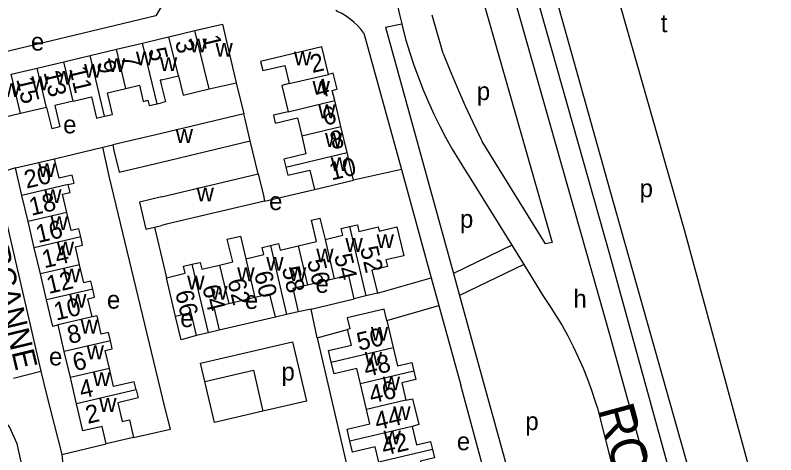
# Model space of a CAD drawing. Extents: x 157646 to 159241, y 379213 to 381217.
# Drawn here: x 158967.4 to 159137, y 380874.9 to 380973 of the extents above; entities that cross this region are included whole.
import ezdxf

# ---------------------------------------------------------------- set-up
doc = ezdxf.new("R2010")
doc.units = 0
for name, color, linetype in [('BLT_Basislijn', 7, 'Continuous'), ('BLT_Bebouwing', 7, 'Continuous'), ('BLT_Centroide', 7, 'Continuous'), ('BLT_Huisnummer', 7, 'Continuous'), ('BLT_Huisnummer_ tussenligend', 7, 'Continuous'), ('BLT_Onderverdeling_panden', 7, 'Continuous'), ('BLT_Straatnaam', 7, 'Continuous'), ('BLT_Straatnaam_hoofdweg', 7, 'Continuous')]:
    doc.layers.add(name, color=color, linetype=linetype)

msp = doc.modelspace()

# ---------------------------------------------------------------- linework, layer by layer
at = {"layer": 'BLT_Basislijn'}
for p, q in [((159062.85, 380964.45), (159060.36, 380973)), ((159049.95, 380970.32), (159053.58, 380971.02)), ((159049.95, 380970.32), (159065.11, 380915.31)), ((159045.13, 380968.99), (159053.52, 380938.55)), ((159016.64, 380957.89), (159018.38, 380950.98)), ((159021.58, 380937.58), (159019.82, 380944.91)), ((158976.19, 380940.93), (158986.93, 380943.49)), ((158986.93, 380943.49), (158989.15, 380944.01)), ((158967.46, 380938.89), (158962.92, 380937.51)), ((159053.52, 380938.55), (159042.86, 380936.15)), ((159053.52, 380938.55), (159060.19, 380914.35)), ((158962.92, 380937.51), (158973.14, 380893.55)), ((159068.63, 380937), (159078.15, 380921.62)), ((159023.02, 380931.49), (159034.13, 380934.08)), ((158998.47, 380925.69), (159001.1, 380914.38)), ((159078.15, 380921.62), (159065.11, 380915.31)), ((159078.15, 380921.62), (159080.79, 380917.35)), ((159080.79, 380917.35), (159066.46, 380910.41)), ((159080.79, 380917.35), (159085.09, 380910.41)), ((159048.15, 380910.92), (159060.19, 380914.35)), ((159060.19, 380914.35), (159061.89, 380908.18)), ((159065.11, 380915.31), (159066.46, 380910.41)), ((159033.39, 380907.39), (159042.99, 380909.7)), ((159066.46, 380910.41), (159071.61, 380891.71)), ((159033.39, 380907.39), (159030.52, 380906.8)), ((159034.75, 380900.98), (159033.39, 380907.39)), ((159050.25, 380904.84), (159061.89, 380908.18)), ((159061.89, 380908.18), (159066.79, 380890.38)), ((159025.41, 380905.59), (159012.87, 380902.69)), ((159034.75, 380900.98), (159041.52, 380902.85)), ((159034.75, 380900.98), (159054.42, 380816.35)), ((158967.04, 380891.93), (158973.14, 380893.55)), ((159084.78, 380823.3), (159066.79, 380890.38)), ((159097.22, 380885.26), (159118.39, 380801.95)), ((158977.78, 380874.89), (158987.68, 380877.29))]:
    msp.add_line(p, q, dxfattribs=at)
for points in [[(159061.42, 381122.18), (159087.3, 381027.91), (159116.68, 380924.86), (159137, 380849.84)], [(159051.94, 381105.75), (159100, 380933.91), (159125.11, 380844.8)], [(159009.95, 380977.12), (159000.45, 380975.73), (158998.72, 380972.84), (158953.4, 380962)], [(159126.48, 380806.41), (159129.85, 380807.86), (159130.83, 380808.7), (159130.78, 380809.42), (159115.53, 380863.06), (159100, 380919.55), (159083.47, 380977.99), (159078.6, 380977.14)], [(159078.6, 380977.14), (159100, 380901.47), (159124.92, 380811.25), (159126.48, 380806.41)], [(159052.45, 380976.01), (159053.07, 380973.13), (159053.58, 380971.02)], [(159071.84, 380975.87), (159087.11, 380922.26), (159085.67, 380921.97), (159071.52, 380944.8)], [(159045.13, 380968.99), (159044.45, 380969.86), (159043.72, 380970.67), (159042.92, 380971.42), (159042.08, 380972.12), (159041.18, 380972.75), (159040.24, 380973.32), (159039.27, 380973.82), (159038.87, 380973.99)], [(159053.58, 380971.02), (159053.76, 380970.27), (159054.53, 380967.42), (159055.38, 380964.6), (159056.31, 380961.8), (159057.31, 380959.03), (159058.39, 380956.29), (159059.54, 380953.57), (159060.76, 380950.89), (159062.06, 380948.24), (159063.42, 380945.63), (159064.86, 380943.06), (159066.37, 380940.53), (159067.94, 380938.03), (159068.63, 380937)], [(159062.85, 380964.45), (159064.38, 380960.57), (159065.99, 380956.71), (159067.67, 380952.89), (159069.42, 380949.09), (159071.25, 380945.34), (159071.52, 380944.8)], [(158993.76, 380878.72), (159002, 380880.56), (159000.73, 380885.48), (158988.42, 380936.73), (158986.93, 380943.49)], [(159085.09, 380910.41), (159086.57, 380908.21), (159087.99, 380905.98), (159089.34, 380903.7), (159090.62, 380901.38), (159091.82, 380899.03), (159092.96, 380896.64), (159094.02, 380894.21), (159095.01, 380891.76), (159095.92, 380889.27), (159096.76, 380886.76), (159097.22, 380885.26)], [(159007.82, 380901.49), (159004.38, 380900.49), (159003.14, 380905.73)], [(159008.74, 380895.28), (159029.23, 380900.1), (159032.35, 380886.86), (159022.65, 380884.58)], [(159009.7, 380891.19), (159008.74, 380895.28)], [(159009.7, 380891.19), (159020.5, 380893.73), (159022.65, 380884.58)], [(158973.14, 380893.55), (158974.36, 380888.3), (158977.78, 380874.89)], [(159022.65, 380884.58), (159011.86, 380882.04), (159009.7, 380891.19)], [(159071.61, 380891.71), (159098.09, 380795.96), (159099.25, 380793.36), (159118.39, 380801.95)], [(158969.46, 380869.92), (158967.87, 380877.27), (158966.12, 380881.08), (158963.78, 380883.86), (158961.67, 380885.68), (158958.02, 380887.53)], [(158977.78, 380874.89), (158978.11, 380872.12), (158969.46, 380869.92)]]:
    msp.add_lwpolyline(points, dxfattribs=at)
at = {"layer": 'BLT_Bebouwing'}
for p, q in [((159007.49, 380969.53), (159013.63, 380970.99)), ((159001.68, 380968.14), (159007.49, 380969.53)), ((158989.98, 380965.37), (158995.81, 380966.75)), ((158995.81, 380966.75), (159000.01, 380967.74)), ((159000.01, 380967.74), (159001.68, 380968.14)), ((158984.09, 380963.98), (158989.98, 380965.37)), ((158978.21, 380962.58), (158984.09, 380963.98)), ((158972.32, 380961.18), (158978.21, 380962.58)), ((158966.5, 380959.81), (158972.32, 380961.18)), ((159000, 380958.57), (159003.79, 380959.47)), ((158999.03, 380953.19), (159000, 380953.42)), ((159040.02, 380948.11), (159038.65, 380953.91)), ((158974.41, 380952.38), (158975.54, 380947.59)), ((159018.38, 380950.98), (159000, 380946.58)), ((159041.4, 380942.3), (159040.02, 380948.11)), ((159000, 380946.58), (158989.15, 380944.01)), ((159000, 380940.18), (159019.82, 380944.91)), ((159042.86, 380936.15), (159041.4, 380942.3)), ((158968.9, 380932.75), (158967.46, 380938.89)), ((159000, 380932.44), (159021.58, 380937.58)), ((159034.13, 380934.08), (159042.86, 380936.15)), ((158970.27, 380926.91), (158968.9, 380932.75)), ((158971.64, 380921.04), (158970.27, 380926.91)), ((158998.47, 380925.69), (159000, 380926.06)), ((158973.01, 380915.22), (158971.64, 380921.04)), ((158974.37, 380909.41), (158973.01, 380915.22)), ((159003.14, 380905.73), (159001.1, 380914.38)), ((159038.55, 380914.13), (159032.59, 380912.72)), ((159048.15, 380910.92), (159045.57, 380910.31)), ((159020.86, 380909.96), (159015, 380908.57)), ((159045.57, 380910.31), (159042.99, 380909.7)), ((159027.93, 380906.19), (159025.41, 380905.59)), ((159030.52, 380906.8), (159027.93, 380906.19)), ((158978.34, 380897.91), (158976.95, 380903.84)), ((159012.87, 380902.69), (159010.39, 380902.1)), ((159010.39, 380902.1), (159007.82, 380901.49)), ((158979.71, 380892.08), (158978.34, 380897.91)), ((158981.08, 380886.24), (158979.71, 380892.08)), ((159045.72, 380884.95), (159044.36, 380890.71))]:
    msp.add_line(p, q, dxfattribs=at)
for points in [[(159013.63, 380970.99), (159014.72, 380966.11), (159016.64, 380957.89)], [(159037.26, 380959.77), (159035.81, 380965.89), (159022.12, 380962.65), (159022.6, 380960.6), (159027.5, 380961.76), (159028.47, 380957.69)], [(159038.65, 380953.91), (159038.11, 380956.19), (159039.18, 380956.44), (159038.33, 380960.03), (159037.26, 380959.77)], [(159000, 380958.57), (158999.73, 380958.5), (158999.97, 380957.5)], [(159003.79, 380959.47), (159004.82, 380955.12), (159010.65, 380956.51)], [(158987.31, 380950.41), (158989.1, 380950.83), (158987.97, 380955.64), (158992.05, 380956.61)], [(158992.05, 380956.61), (158995.11, 380957.33), (158995.96, 380953.73), (158996.99, 380953.98), (158997.28, 380952.78), (158999.03, 380953.19)], [(158999.97, 380957.5), (159000.88, 380953.63), (159000, 380953.42)], [(159010.65, 380956.51), (159016.64, 380957.89)], [(159028.47, 380957.69), (159026.84, 380957.3), (159028.23, 380951.44)], [(158980.3, 380953.77), (158976.22, 380952.81), (158977.35, 380948.02), (158975.54, 380947.59)], [(158980.3, 380953.77), (158984.38, 380954.74), (158985.51, 380949.98), (158987.31, 380950.41)], [(158974.41, 380952.38), (158968.59, 380951)], [(159028.23, 380951.44), (159024.98, 380950.67), (159025.4, 380948.88), (159030.34, 380950.05), (159031.29, 380946.04)], [(158968.59, 380951), (158964.59, 380950.05), (158964.96, 380948.48), (158963.19, 380948.06)], [(159019.82, 380944.91), (159018.67, 380949.77), (159018.38, 380950.98)], [(159031.29, 380946.04), (159032.24, 380942.03), (159027.33, 380940.87), (159027.75, 380939.06)], [(158989.15, 380944.01), (158989.42, 380942.81), (158990.57, 380937.95), (159000, 380940.18)], [(158967.46, 380938.89), (158972.33, 380940.03), (158976.19, 380940.93)], [(158979.21, 380935.17), (158980.53, 380935.49), (158980.12, 380937.27), (158978.79, 380936.96), (158977.21, 380936.59), (158976.19, 380940.93)], [(159027.75, 380939.06), (159028.18, 380937.25), (159033.1, 380938.42), (159034.13, 380934.08)], [(159021.58, 380937.58), (159022.73, 380932.71), (159023.02, 380931.49)], [(158978.93, 380928.94), (158977.98, 380933), (158979.63, 380933.39), (158979.21, 380935.17)], [(159000, 380932.44), (158995.12, 380931.27), (158996.55, 380925.24), (158998.47, 380925.69)], [(159023.02, 380931.49), (159001.42, 380926.39), (159000, 380926.06)], [(158982, 380923.47), (158981.57, 380925.29), (158979.88, 380924.89), (158978.93, 380928.94)], [(159030.52, 380921.46), (159034.59, 380922.43), (159033.45, 380927.25), (159035.34, 380927.69), (159036.48, 380922.89)], [(159041.91, 380925.78), (159043.7, 380926.21), (159044.06, 380924.72), (159048.34, 380925.73), (159048.57, 380924.79), (159052.53, 380925.73), (159054.05, 380919.3), (159050.08, 380918.36), (159050.42, 380916.92), (159046.93, 380916.1), (159048.15, 380910.92)], [(159036.48, 380922.89), (159040.48, 380923.84), (159040.12, 380925.36), (159041.91, 380925.78)], [(158981.75, 380917.27), (158980.81, 380921.28), (158982.42, 380921.66), (158982, 380923.47)], [(159012.96, 380917.21), (159015.9, 380917.9), (159014.7, 380922.98), (159017.62, 380923.67), (159018.82, 380918.61)], [(159018.82, 380918.61), (159022.86, 380919.57), (159022.49, 380921.13), (159024.3, 380921.56)], [(159024.3, 380921.56), (159026.11, 380921.99), (159026.46, 380920.5), (159030.52, 380921.46)], [(159006.78, 380917.37), (159008.62, 380917.8), (159008.98, 380916.27), (159012.96, 380917.21)], [(158984.68, 380911.83), (158984.26, 380913.62), (158982.69, 380913.26), (158981.75, 380917.27)], [(159001.1, 380914.38), (159005.32, 380915.37), (159004.95, 380916.93), (159006.78, 380917.37)], [(159042.99, 380909.7), (159041.77, 380914.89), (159038.55, 380914.13)], [(159032.59, 380912.72), (159029.3, 380911.94), (159030.52, 380906.8)], [(158984.54, 380905.62), (158983.59, 380909.68), (158985.1, 380910.04), (158984.68, 380911.83)], [(159025.41, 380905.59), (159024.19, 380910.74), (159020.86, 380909.96)], [(158976.95, 380903.84), (158975.77, 380903.46), (158974.37, 380909.41)], [(159015, 380908.57), (159011.67, 380907.79), (159012.87, 380902.69)], [(159050.25, 380904.84), (159049.65, 380907.36), (159041.4, 380905.41), (159041.98, 380902.96), (159041.52, 380902.85)], [(158988.63, 380900.33), (158988.21, 380902.13), (158986.6, 380901.75), (158985.64, 380905.87), (158984.54, 380905.62)], [(159007.82, 380901.49), (159006.63, 380906.56), (159003.14, 380905.73)], [(159050.25, 380904.84), (159051.67, 380898.79)], [(159037.88, 380895.53), (159037.27, 380898.1), (159042.36, 380899.3), (159041.52, 380902.85)], [(158988.4, 380894.12), (158987.46, 380898.15), (158989.05, 380898.52), (158988.63, 380900.33)], [(159051.67, 380898.79), (159052.65, 380894.68), (159055.87, 380895.44), (159056.32, 380893.54)], [(159044.36, 380890.71), (159043.55, 380894.15), (159038.49, 380892.96), (159037.88, 380895.53)], [(158994.39, 380889.33), (158993.96, 380891.17), (158989.35, 380890.09), (158988.4, 380894.12)], [(159056.32, 380893.54), (159056.77, 380891.64), (159053.61, 380890.89), (159054.52, 380887.03)], [(158994.39, 380889.33), (158994.81, 380887.55), (158990.26, 380886.48), (158991.25, 380882.26), (158992.85, 380882.63), (158993.76, 380878.72)], [(159054.52, 380887.03), (159056, 380887.38), (159057.37, 380881.63), (159055.92, 380881.16)], [(158987.68, 380877.29), (158986.76, 380881.2), (158982.49, 380880.2), (158981.08, 380886.24)], [(159042.04, 380877.88), (159041.4, 380880.56), (159046.48, 380881.77), (159045.72, 380884.95)], [(159055.92, 380881.16), (159056.88, 380877.1), (159060.04, 380877.85), (159060.47, 380876.02)], [(158993.76, 380878.72), (158987.68, 380877.29)], [(159048.48, 380873.18), (159047.67, 380876.61), (159042.62, 380875.41), (159042.04, 380877.88)], [(159060.47, 380876.02), (159060.91, 380874.18), (159057.76, 380873.44), (159058.68, 380869.58)]]:
    msp.add_lwpolyline(points, dxfattribs=at)
at = {"layer": 'BLT_Onderverdeling_panden'}
for p, q in [((159010.65, 380956.51), (159007.49, 380969.53)), ((158999.03, 380953.19), (158995.81, 380966.75)), ((159003.79, 380959.47), (159001.68, 380968.14)), ((158992.05, 380956.61), (158989.98, 380965.37)), ((158987.31, 380950.41), (158984.09, 380963.98)), ((158980.3, 380953.77), (158978.21, 380962.58)), ((158974.41, 380952.38), (158972.32, 380961.18)), ((158968.59, 380951), (158966.5, 380959.81)), ((159028.47, 380957.69), (159037.26, 380959.77)), ((159028.23, 380951.44), (159038.65, 380953.91)), ((159031.29, 380946.04), (159040.02, 380948.11)), ((159027.75, 380939.06), (159041.4, 380942.3)), ((158979.21, 380935.17), (158968.9, 380932.75)), ((158978.93, 380928.94), (158970.27, 380926.91)), ((159041.91, 380925.78), (159045.57, 380910.31)), ((158982, 380923.47), (158971.64, 380921.04)), ((159036.48, 380922.89), (159038.55, 380914.13)), ((159024.3, 380921.56), (159027.93, 380906.19)), ((159030.52, 380921.46), (159032.59, 380912.72)), ((159018.82, 380918.61), (159020.86, 380909.96)), ((158981.75, 380917.27), (158973.01, 380915.22)), ((159006.78, 380917.37), (159010.39, 380902.1)), ((159012.96, 380917.21), (159015, 380908.57)), ((158984.68, 380911.83), (158974.37, 380909.41)), ((158984.54, 380905.62), (158976.95, 380903.84)), ((158988.63, 380900.33), (158978.34, 380897.91)), ((159037.88, 380895.53), (159051.67, 380898.79)), ((158988.4, 380894.12), (158979.71, 380892.08)), ((159056.32, 380893.54), (159044.36, 380890.71)), ((158994.39, 380889.33), (158981.08, 380886.24)), ((159054.52, 380887.03), (159045.72, 380884.95)), ((159055.92, 380881.16), (159042.04, 380877.88)), ((159060.47, 380876.02), (159048.48, 380873.18))]:
    msp.add_line(p, q, dxfattribs=at)

# ---------------------------------------------------------------- texts
at = {"layer": 'BLT_Centroide'}
for s, p in [('t', (159111.34, 380969.18)), ('e', (158970.89, 380965.07)), ('w', (159006.27, 380964.66)), ('w', (159012.06, 380963.73)), ('w', (158988.08, 380960.28)), ('w', (158994.31, 380961.78)), ('w', (158999.66, 380960.5)), ('w', (159029.55, 380961.78)), ('w', (158982.77, 380959)), ('w', (158976.31, 380957.47)), ('w', (158971.02, 380956.22)), ('w', (159033.7, 380955.22)), ('w', (158964.66, 380954.72)), ('p', (159070.33, 380954.02)), ('w', (159034.97, 380949.97)), ('e', (158978.09, 380946.6)), ('w', (159003.18, 380944.47)), ('w', (159036.48, 380943.59)), ('w', (159037.77, 380938.19)), ('w', (158972.55, 380936.84)), ('w', (159007.85, 380931.41)), ('p', (159106.65, 380932.35)), ('w', (158973.87, 380931.03)), ('e', (159024.01, 380929.48)), ('w', (158975.29, 380925)), ('p', (159066.58, 380925.52)), ('w', (159041.03, 380920.14)), ('w', (159047.98, 380921)), ('w', (158976.66, 380919.34)), ('w', (159034.53, 380917.8)), ('w', (159023.38, 380915.95)), ('w', (158978.06, 380913.34)), ('w', (159016.91, 380913.59)), ('w', (159028.44, 380913.64)), ('w', (159005.75, 380911.73)), ('e', (159034.37, 380911.01)), ('w', (159010.89, 380909.47)), ('w', (158979.42, 380907.66)), ('h', (159091.87, 380907.69)), ('e', (158987.85, 380907.48)), ('e', (159018.61, 380907.41)), ('e', (159004.2, 380903.36)), ('w', (158981.98, 380901.91)), ('w', (159046.71, 380900.34)), ('w', (158983.32, 380896.19)), ('e', (158974.94, 380894.8)), ('w', (159045.34, 380894.75)), ('p', (159026.77, 380891.44)), ('w', (158984.74, 380890.19)), ('w', (159049.35, 380889.25)), ('w', (158986.12, 380884.44)), ('w', (159051.7, 380882.62)), ('p', (159081.16, 380880.37)), ('w', (159049.53, 380877.16)), ('e', (159065.88, 380875.88))]:
    msp.add_text(s, height=4, dxfattribs=at).set_placement(p)
at = {"layer": 'BLT_Huisnummer'}
for s, rotation, p in [('1', 283.3282, (159009.06, 380968.11)), ('5', 283.3282, (158997.01, 380965.3)), ('2', 13.3244, (159033.67, 380960.04)), ('9', 283.3282, (158985.56, 380962.47)), ('13', 283.3282, (158973.7, 380960.22)), ('6', 13.3378, (159036.43, 380948.27)), ('10', 13.3239, (159037.95, 380936.08)), ('20', 13.2055, (158969.9, 380934.25)), ('14', 13.1989, (158973.88, 380916.47)), ('52', 283.3107, (159044.27, 380920.97)), ('56', 283.3033, (159032.46, 380918.14)), ('60', 283.3095, (159020.64, 380915.41)), ('66', 283.3017, (159003.04, 380911.15)), ('10', 13.1875, (158976.52, 380904.8)), ('50', 13.3055, (159044.08, 380898.05)), ('6', 13.1997, (158980.73, 380893.48)), ('2', 13.2004, (158983.57, 380881.74)), ('44', 13.3055, (159048.06, 380880.33))]:
    msp.add_text(s, height=4, rotation=rotation, dxfattribs=at).set_placement(p)
at = {"layer": 'BLT_Huisnummer_ tussenligend'}
for s, rotation, p in [('3', 283.3282, (159003.03, 380967.03)), ('7', 283.3282, (158990.93, 380963.79)), ('11', 283.3282, (158979.4, 380961.09)), ('15', 283.3282, (158967.61, 380958.7)), ('4', 13.3244, (159034.87, 380954.4)), ('8', 13.3378, (159038.11, 380942.94)), ('18', 13.1989, (158971, 380928.19)), ('16', 13.1989, (158972.51, 380922.1)), ('54', 283.3107, (159038.49, 380919.31)), ('12', 13.1875, (158974.87, 380910.74)), ('58', 283.3033, (159026.84, 380916.46)), ('62', 283.3095, (159014.71, 380913.72)), ('64', 283.3095, (159009.08, 380912.36)), ('8', 13.1997, (158979.52, 380899.57)), ('48', 13.3055, (159045.63, 380892.2)), ('4', 13.2004, (158982.19, 380887.36)), ('46', 13.3055, (159046.84, 380886.26)), ('42', 13.3055, (159049.6, 380874.63))]:
    msp.add_text(s, height=4, rotation=rotation, dxfattribs=at).set_placement(p)
at = {"layer": 'BLT_Straatnaam'}
msp.add_text('NEERCANNE', height=5, rotation=283.5139, dxfattribs=at).set_placement((158957.78, 380934.28))
at = {"layer": 'BLT_Straatnaam_hoofdweg'}
msp.add_text('ROFFART', height=8, rotation=285.155, dxfattribs=at).set_placement((159097.31, 380885.05))

doc.saveas('drawing.dxf')
